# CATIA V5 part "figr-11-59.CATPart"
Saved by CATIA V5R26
Part number: Part1
Bounding box of the stored display mesh (mm): x -59.829 to 59.829, y -71.429 to 72.174, z -61 to 76
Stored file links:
  D:\_Deepak\CATIA\CATIA V5-6R2016_Deepak\Resources\Part files\Partfiles\c11_catia_v5_6r2016_prt\figr-11-59.CATPart
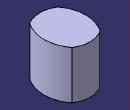
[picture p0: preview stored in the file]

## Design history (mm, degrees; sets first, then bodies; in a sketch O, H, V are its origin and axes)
Set1
  Extrude1: Element1 Sketch1, Lim1 76, Lim2 61, Direction xy-plane
Body1 (main body)
  Sketch1 on xy-plane, origin (0, 0, 0), H (0, 1, 0), V (-1, 0, 0)
    arc A1 centre (0, -40) radius 100 from (-60, 40) to (60, 40) cw
    point P2 (0, 60)
    point P3 (-60, 40)
    point P4 (60, 40)
    axis line L1 (-90, 0) -> (80, 0)
    point P6 (80, 0)
    point P7 (60, -40)
    point P8 (-60, -40)
    arc A2 centre (0, 40) radius 100 from (-60, -40) to (60, -40) ccw
    arc A3 centre (4.2857, 0) radius 75.7143 from (-60, 40) to (-60, -40) ccw
    arc A4 centre (0.3727, 0) radius 71.8012 from (60, -40) to (60, 40) ccw
    coincidence: A1 P2, P2 V, A3 P6
    horizontal: L1 H
    symmetry: P4 P7 L1, P3 P8 L1, A1 A2 L1
    tangency: A4 A3
  Sketch2 on xy-plane, origin (0, 0, 0), H (1, 0, 0), V (0, 1, 0)
    spline S1 through (80, 90) (60, 60) (70, 0) (50, -50) (50, -80)
    point P1 (70, 0)
    coincidence: P1 H
  CloseSurface1: CloseElement Extrude1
